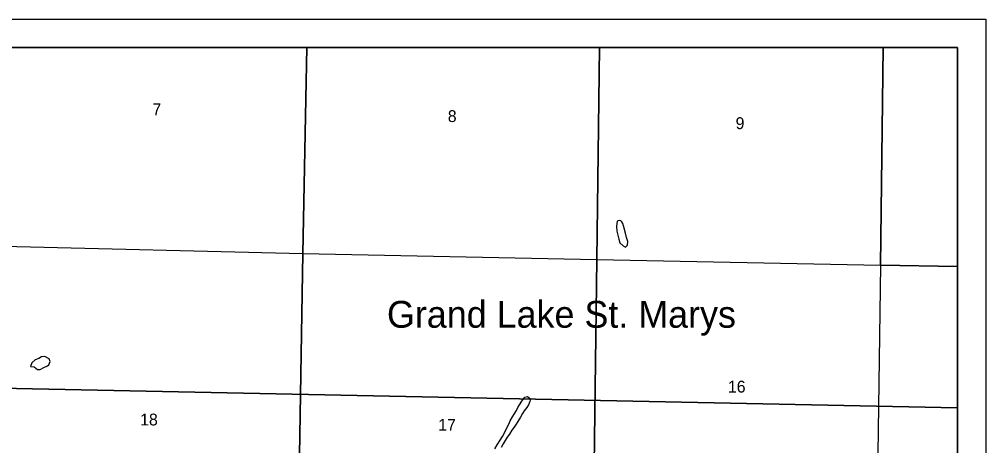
# Model space of a CAD drawing. Extents: x -38.1 to 35.9, y -2.7 to 28.5.
# Drawn here: x 22.099 to 25.51, y 18.326 to 19.831 of the extents above; entities that cross this region are included whole.
import ezdxf

# ---------------------------------------------------------------- set-up
doc = ezdxf.new("R2010")
doc.units = 0
for name, color, linetype in [('GM_X_Interstate_Shield', 7, 'Continuous'), ('GM_X_Minor_River', 7, 'Continuous'), ('GM_X_State_Shield', 7, 'Continuous'), ('GM_X_US_Route', 7, 'Continuous'), ('SH_Border', 7, 'Continuous'), ('SH_Data', 7, 'Continuous')]:
    doc.layers.add(name, color=color, linetype=linetype)

msp = doc.modelspace()

# ---------------------------------------------------------------- linework, layer by layer
at = {"layer": 'GM_X_Interstate_Shield'}
for points in [[(24.2289, 19.1105), (24.2264, 19.1159), (24.2224, 19.1191), (24.2171, 19.12), (24.2132, 19.119), (24.2098, 19.1179), (24.208, 19.1096), (24.207, 19.0994), (24.2087, 19.0823), (24.2114, 19.0682), (24.2148, 19.0548), (24.2193, 19.0421)], [(24.2193, 19.0421), (24.23, 19.0316), (24.239, 19.0264), (24.246, 19.0334), (24.2475, 19.0462), (24.2426, 19.06), (24.2385, 19.0757), (24.2341, 19.0929), (24.2289, 19.1105)], [(22.1678, 18.6339), (22.1552, 18.6286), (22.1435, 18.6183), (22.1385, 18.6052), (22.1518, 18.6036), (22.1633, 18.595), (22.1728, 18.5943), (22.1859, 18.6019), (22.1982, 18.6073)], [(22.1775, 18.6397), (22.1678, 18.6339)], [(22.1982, 18.6073), (22.2029, 18.6105), (22.2082, 18.6225), (22.205, 18.6321), (22.1897, 18.6401), (22.1775, 18.6397)], [(23.7777, 18.3143), (23.786, 18.3281), (23.7968, 18.3456), (23.8044, 18.3583), (23.8116, 18.3714), (23.8201, 18.3889), (23.827, 18.402), (23.8319, 18.4129), (23.8395, 18.4271), (23.8455, 18.4372), (23.8535, 18.4498), (23.8587, 18.4599), (23.8647, 18.47), (23.8731, 18.483), (23.8833, 18.4964), (23.8933, 18.4991), (23.9033, 18.4912), (23.9015, 18.4811), (23.8959, 18.4702), (23.8902, 18.4605), (23.8812, 18.449), (23.8748, 18.439), (23.868, 18.4262), (23.8588, 18.411), (23.8528, 18.4013), (23.8453, 18.3909), (23.8381, 18.3808), (23.829, 18.3667), (23.821, 18.3551), (23.8135, 18.3444), (23.8067, 18.332), (23.8002, 18.3197)]]:
    msp.add_lwpolyline(points, dxfattribs=at)
at = {"layer": 'GM_X_US_Route'}
for points in [[(22.0312, 18.5289), (25.4101, 18.4589), (25.4101, 19.7308), (18.6101, 19.7308)], [(25.4101, 13.9853), (25.4101, 18.4589), (22.0312, 18.5289)]]:
    msp.add_lwpolyline(points, dxfattribs=at)
for points in [[(23.1141, 19.7308), (22.0631, 19.7308), (22.0424, 19.0296), (23.1004, 19.0039)], [(24.147, 19.7308), (23.1141, 19.7308), (23.1004, 19.0039), (24.1377, 18.9829)], [(25.1485, 19.7308), (24.147, 19.7308), (24.1377, 18.9829), (25.1383, 18.963)], [(25.4101, 18.9578), (25.4101, 19.7308), (25.1485, 19.7308), (25.1383, 18.963)], [(23.1004, 19.0039), (23.0833, 18.0071), (22.0145, 18.0265), (22.0424, 19.0296)], [(23.1004, 19.0039), (24.1377, 18.9829), (24.1248, 17.9867), (23.0833, 18.0071)], [(25.1383, 18.963), (25.1245, 17.9642), (24.1248, 17.9867), (24.1377, 18.9829)], [(25.4101, 17.9572), (25.4101, 18.9578), (25.1383, 18.963), (25.1245, 17.9642)]]:
    msp.add_lwpolyline(points, close=True, dxfattribs=at)
at = {"layer": 'SH_Border'}
for p, q in [((18.6101, 19.7308), (25.4101, 19.7308)), ((25.4101, 19.7308), (25.4101, 12.9308))]:
    msp.add_line(p, q, dxfattribs=at)
at = {"layer": 'SH_Data'}
for p, q in [((18.5101, 19.8308), (25.5101, 19.8308)), ((25.5101, 19.8308), (25.5101, 12.8308))]:
    msp.add_line(p, q, dxfattribs=at)

# ---------------------------------------------------------------- texts
at = {"layer": 'GM_X_Minor_River'}
for s, height, p in [('7', 0.0419, (22.569, 19.492)), ('8', 0.0419, (23.6115, 19.4681)), ('9', 0.0419, (24.6274, 19.4431)), ('16', 0.04186, (24.6003, 18.5131)), ('18', 0.04186, (22.5257, 18.3969)), ('17', 0.04186, (23.5778, 18.3782))]:
    msp.add_text(s, height=height, rotation=0, dxfattribs=at).set_placement(p)
at = {"layer": 'GM_X_State_Shield'}
msp.add_text('Grand Lake St. Marys', height=0.094709, dxfattribs=at).set_placement((23.3968, 18.742))

doc.saveas('drawing.dxf')
